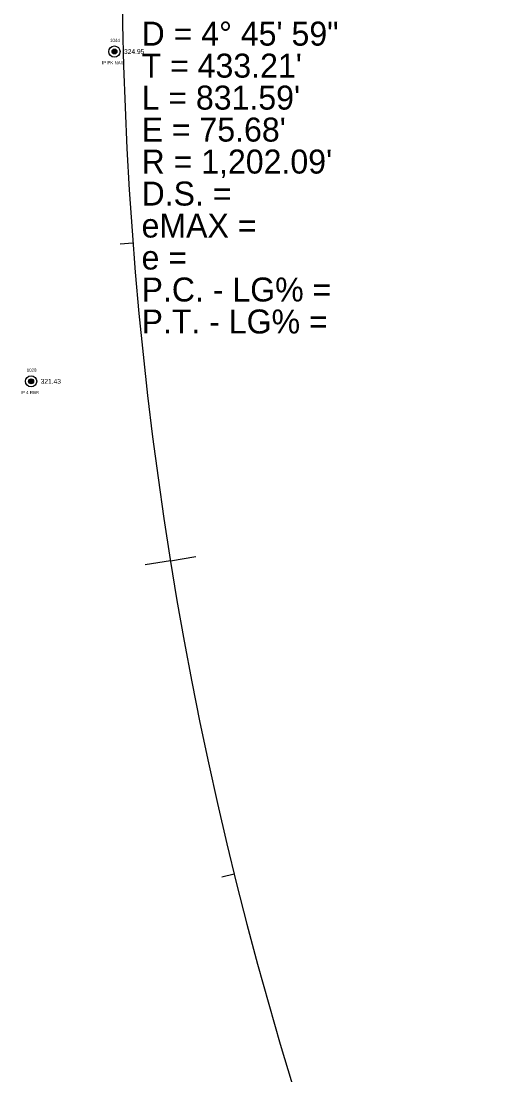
# Model space of a CAD drawing. Extents: x 1865045 to 1867370, y 910391 to 914218.
# Drawn here: x 1865883.3 to 1866035, y 911975.2 to 912304.7 of the extents above; entities that cross this region are included whole.
import ezdxf

# ---------------------------------------------------------------- set-up
doc = ezdxf.new("R2010")
doc.units = 0
for name, color, linetype in [('RD_EX_DV_Prop_txCode', 7, 'Continuous'), ('RD_EX_DV_PropPin', 7, 'Continuous'), ('RD_EX_TX_DV_Prop_ELEV', 7, 'Continuous'), ('RD_HC_Cl', 7, 'Continuous'), ('RD_HC_Data', 7, 'Continuous'), ('RD_HC_Data_Tic', 7, 'Continuous'), ('RD_SMD_Locator', 7, 'Continuous')]:
    doc.layers.add(name, color=color, linetype=linetype)

msp = doc.modelspace()

# ---------------------------------------------------------------- linework, layer by layer
at = {"layer": 'RD_EX_DV_PropPin'}
for p, q in [((1865911.8, 912294.96), (1865911.8, 912295.35)), ((1865911.83, 912294.85), (1865911.83, 912295.45)), ((1865911.87, 912294.78), (1865911.87, 912295.52)), ((1865911.9, 912294.72), (1865911.9, 912295.58)), ((1865911.94, 912294.68), (1865911.94, 912295.63)), ((1865911.97, 912294.64), (1865911.97, 912295.67)), ((1865912.01, 912294.6), (1865912.01, 912295.7)), ((1865912.04, 912294.57), (1865912.04, 912295.73)), ((1865912.08, 912294.54), (1865912.08, 912295.76)), ((1865912.11, 912294.52), (1865912.11, 912295.79)), ((1865912.15, 912294.49), (1865912.15, 912295.81)), ((1865912.18, 912294.48), (1865912.18, 912295.83)), ((1865912.22, 912294.46), (1865912.22, 912295.84)), ((1865912.25, 912294.44), (1865912.25, 912295.86)), ((1865912.29, 912294.43), (1865912.29, 912295.87)), ((1865912.32, 912294.42), (1865912.32, 912295.88)), ((1865912.36, 912294.41), (1865912.36, 912295.89)), ((1865912.39, 912294.4), (1865912.39, 912295.9)), ((1865912.43, 912294.4), (1865912.43, 912295.91)), ((1865912.46, 912294.39), (1865912.46, 912295.91)), ((1865912.5, 912294.39), (1865912.5, 912295.91)), ((1865912.53, 912294.39), (1865912.53, 912295.91)), ((1865912.57, 912294.39), (1865912.57, 912295.91)), ((1865912.6, 912294.39), (1865912.6, 912295.91)), ((1865912.64, 912294.4), (1865912.64, 912295.91)), ((1865912.67, 912294.4), (1865912.67, 912295.9)), ((1865912.71, 912294.41), (1865912.71, 912295.89)), ((1865912.74, 912294.42), (1865912.74, 912295.88)), ((1865912.78, 912294.43), (1865912.78, 912295.87)), ((1865912.81, 912294.44), (1865912.81, 912295.86)), ((1865912.85, 912294.46), (1865912.85, 912295.84)), ((1865912.88, 912294.48), (1865912.88, 912295.83)), ((1865912.92, 912294.49), (1865912.92, 912295.81)), ((1865912.95, 912294.52), (1865912.95, 912295.79)), ((1865912.99, 912294.54), (1865912.99, 912295.76)), ((1865913.02, 912294.57), (1865913.02, 912295.73)), ((1865913.06, 912294.6), (1865913.06, 912295.7)), ((1865913.09, 912294.64), (1865913.09, 912295.67)), ((1865913.13, 912294.68), (1865913.13, 912295.63)), ((1865913.16, 912294.72), (1865913.16, 912295.58)), ((1865913.2, 912294.78), (1865913.2, 912295.52)), ((1865913.23, 912294.85), (1865913.23, 912295.45)), ((1865913.27, 912294.96), (1865913.27, 912295.35)), ((1865885.89, 912191.54), (1865885.89, 912192.57)), ((1865885.93, 912191.5), (1865885.93, 912192.6)), ((1865885.96, 912191.47), (1865885.96, 912192.63)), ((1865886, 912191.44), (1865886, 912192.66)), ((1865886.03, 912191.42), (1865886.03, 912192.69)), ((1865886.07, 912191.4), (1865886.07, 912192.71)), ((1865886.1, 912191.38), (1865886.1, 912192.73)), ((1865886.14, 912191.36), (1865886.14, 912192.75)), ((1865886.17, 912191.35), (1865886.17, 912192.76)), ((1865886.21, 912191.33), (1865886.21, 912192.77)), ((1865886.24, 912191.32), (1865886.24, 912192.78)), ((1865886.28, 912191.31), (1865886.28, 912192.79)), ((1865886.31, 912191.3), (1865886.31, 912192.8)), ((1865886.35, 912191.3), (1865886.35, 912192.81)), ((1865886.38, 912191.29), (1865886.38, 912192.81)), ((1865886.42, 912191.29), (1865886.42, 912192.81)), ((1865886.45, 912191.29), (1865886.45, 912192.81)), ((1865886.49, 912191.29), (1865886.49, 912192.81)), ((1865886.52, 912191.29), (1865886.52, 912192.81)), ((1865886.56, 912191.3), (1865886.56, 912192.81)), ((1865886.59, 912191.3), (1865886.59, 912192.8)), ((1865886.63, 912191.31), (1865886.63, 912192.79)), ((1865886.66, 912191.32), (1865886.66, 912192.78)), ((1865886.7, 912191.33), (1865886.7, 912192.77)), ((1865886.73, 912191.35), (1865886.73, 912192.76)), ((1865886.77, 912191.36), (1865886.77, 912192.75)), ((1865886.8, 912191.38), (1865886.8, 912192.73)), ((1865886.84, 912191.4), (1865886.84, 912192.71)), ((1865886.87, 912191.42), (1865886.87, 912192.69)), ((1865886.91, 912191.44), (1865886.91, 912192.66)), ((1865886.94, 912191.47), (1865886.94, 912192.63)), ((1865886.98, 912191.5), (1865886.98, 912192.6)), ((1865887.01, 912191.54), (1865887.01, 912192.57)), ((1865885.72, 912191.86), (1865885.72, 912192.25)), ((1865885.75, 912191.75), (1865885.75, 912192.35)), ((1865885.79, 912191.68), (1865885.79, 912192.42)), ((1865885.82, 912191.63), (1865885.82, 912192.48)), ((1865885.86, 912191.58), (1865885.86, 912192.53)), ((1865887.05, 912191.58), (1865887.05, 912192.53)), ((1865887.08, 912191.63), (1865887.08, 912192.48)), ((1865887.12, 912191.68), (1865887.12, 912192.42)), ((1865887.15, 912191.75), (1865887.15, 912192.35)), ((1865887.19, 912191.86), (1865887.19, 912192.25))]:
    msp.add_line(p, q, dxfattribs=at)
for centre, radius in [((1865912.53, 912295.15), 1.75), ((1865912.53, 912295.15), 0.761), ((1865886.45, 912192.05), 1.75), ((1865886.45, 912192.05), 0.761)]:
    msp.add_circle(centre, radius, dxfattribs=at)
at = {"layer": 'RD_HC_Cl'}
msp.add_arc((1867116.95, 912326.33), 1202.09, 166.19447, 205.83091, dxfattribs=at)
at = {"layer": 'RD_HC_Data_Tic'}
for p, q in [((1865918.32, 912235.25), (1865914.33, 912234.95)), ((1865930.04, 912135.97), (1865937.93, 912137.24)), ((1865930.04, 912135.97), (1865922.14, 912134.7)), ((1865949.96, 912038), (1865946.07, 912037.04))]:
    msp.add_line(p, q, dxfattribs=at)
at = {"layer": 'RD_SMD_Locator'}
for centre in [(1865912.53, 912295.15), (1865886.45, 912192.05)]:
    msp.add_circle(centre, 0.15, dxfattribs=at)

# ---------------------------------------------------------------- texts
at = {"layer": 'RD_EX_DV_Prop_txCode'}
for s, p in [('1044', (1865911.15, 912298.15)), ('IP PK NAIL', (1865908.64, 912291.15)), ('1028', (1865885.07, 912195.05)), ('IP 4 RBR', (1865883.19, 912188.05))]:
    msp.add_text(s, height=1, dxfattribs=at).set_placement(p)
at = {"layer": 'RD_EX_TX_DV_Prop_ELEV'}
for s, p in [('324.95', (1865915.53, 912294.4)), ('321.43', (1865889.45, 912191.3))]:
    msp.add_text(s, height=1.5, dxfattribs=at).set_placement(p)
at = {"layer": 'RD_HC_Data'}
for s, p in [('D = 4%%d 45\' 59"', (1865921, 912297)), ("T = 433.21'", (1865921, 912287)), ("L = 831.59'", (1865921, 912277)), ("E = 75.68'", (1865921, 912267)), ("R = 1,202.09'", (1865921, 912257)), ('D.S. = ', (1865921, 912247)), ('eMAX = ', (1865921, 912237)), ('e = ', (1865921, 912227)), ('P.C. - LG% = ', (1865921, 912217)), ('P.T. - LG% = ', (1865921, 912207))]:
    msp.add_text(s, height=7.5, dxfattribs=at).set_placement(p)

doc.saveas('drawing.dxf')
